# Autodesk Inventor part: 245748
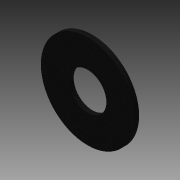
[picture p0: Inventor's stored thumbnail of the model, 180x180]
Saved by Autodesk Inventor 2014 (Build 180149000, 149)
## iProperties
Shininess: 20.0
Length Units: 11272
Angle Units: 11279
Time Units: 11290
Mass Units: 11286
Length Display Precision: 3
Angle Display Precision: 2
Company: Autodesk, Inc.
Created: 2002-07
Part Number: 245748
Material: Silicone
Description: GASKET;A
Document SubType Name: Modeling
Designer: Autodesk, Inc.
Density: 1.25 g/cm^3
Mass: 4.45404 g
Surface Area: 34.9153 cm^2
Volume: 3.56323 cm^3
Appearance: Black Vinyl (texture)
Density: 0.0
Volumn: 0.0
Area: 0.0
PropertySet Name: Model Information
Control State: 0
Master: False
Checked Out: False
Last Check In By: JT
Last Check In Date: 2003-06-20
Title: GASKET;A
Author: Autodesk, Inc.
Revision Number: A
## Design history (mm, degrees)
sketch "Sketch1"
  geometry: C1 r 23.812 at (0, 0); C2 r 9.525 at (0, 0); 1 further point
  constraints: 2 centre point, 2 coincident
  dimensions: "d3" = 47.625 diameter of C1; "d4" = 19.05 diameter of C2
extrude "Extrusion2" new body sketch "Sketch1" distance "d5" = 2.38125; taper "d6" = 0 deg
body "Solid1"
